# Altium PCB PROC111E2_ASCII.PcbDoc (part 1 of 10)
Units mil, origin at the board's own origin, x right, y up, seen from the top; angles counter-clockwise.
Board outline 7700 x 2300 mil, 6 copper layers (Top Layer, GND 1, SIG 1, SIG 2, GND 2, Bottom Layer), stack 78.711 mil thick; 767 components, 596 nets, 2755 pads, 1578 vias.
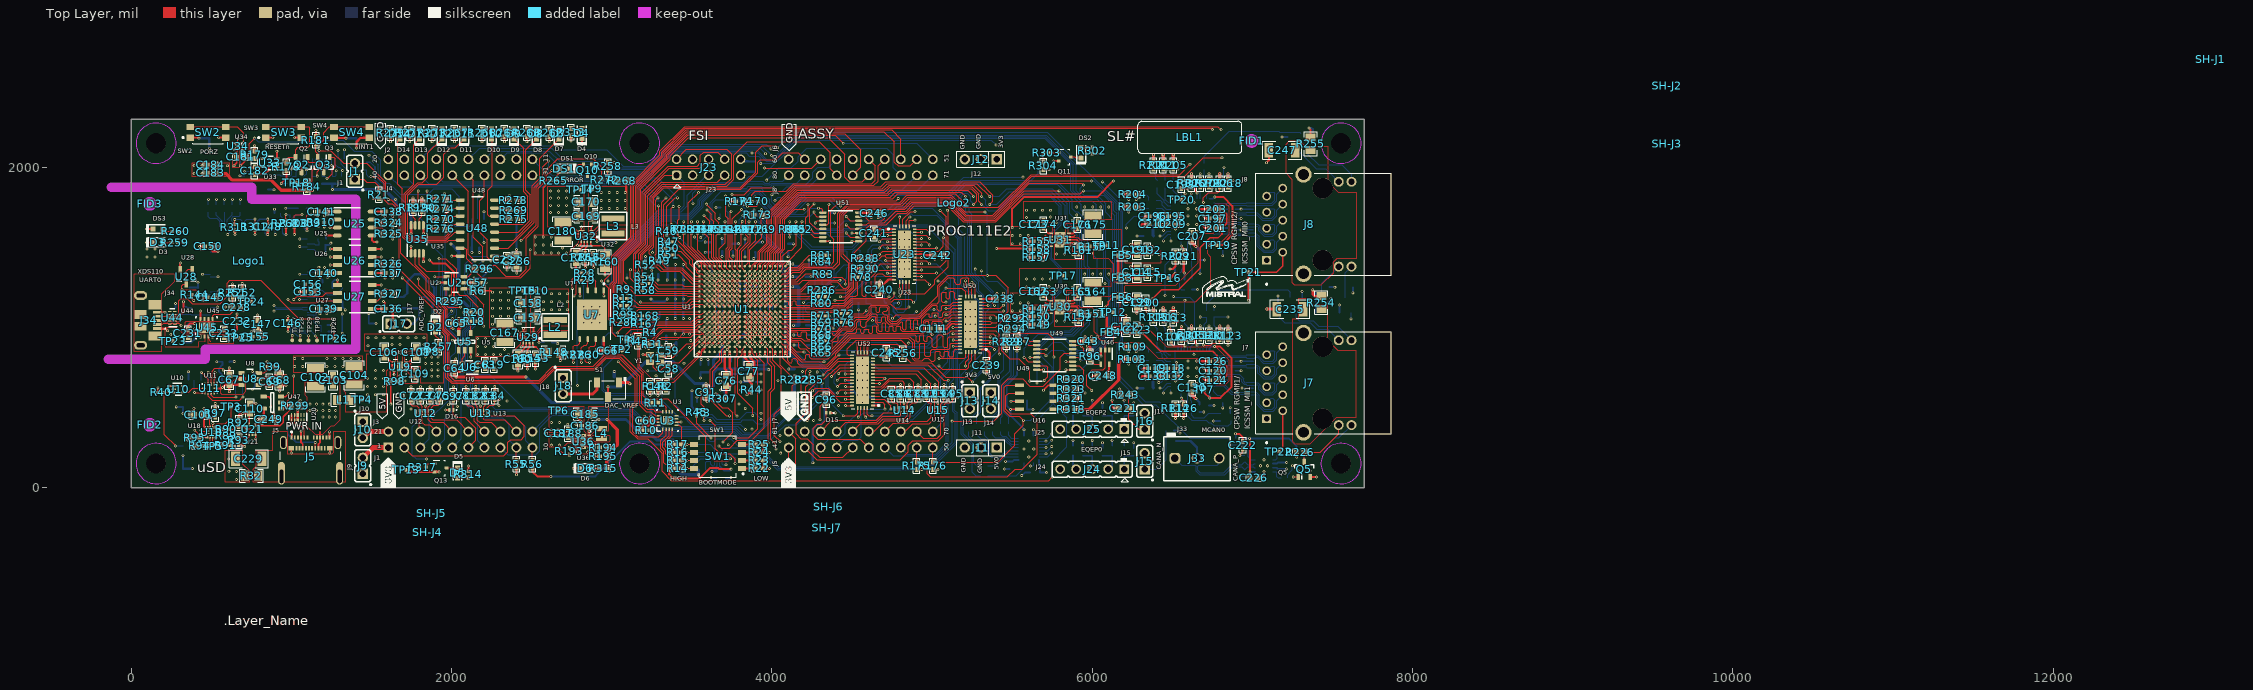
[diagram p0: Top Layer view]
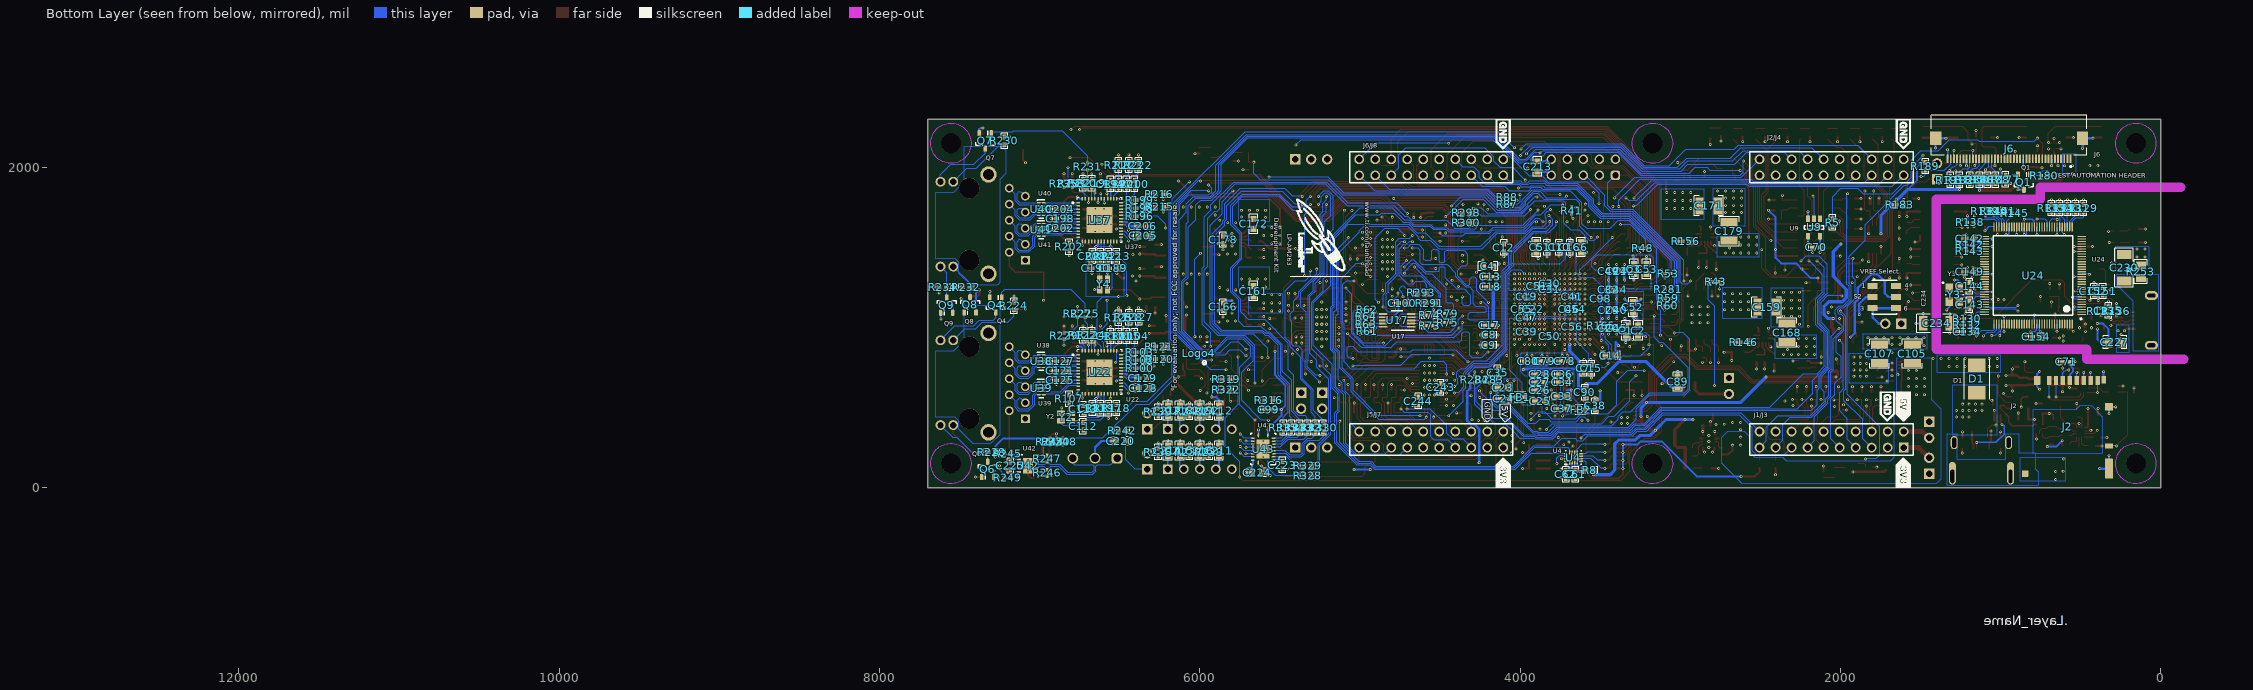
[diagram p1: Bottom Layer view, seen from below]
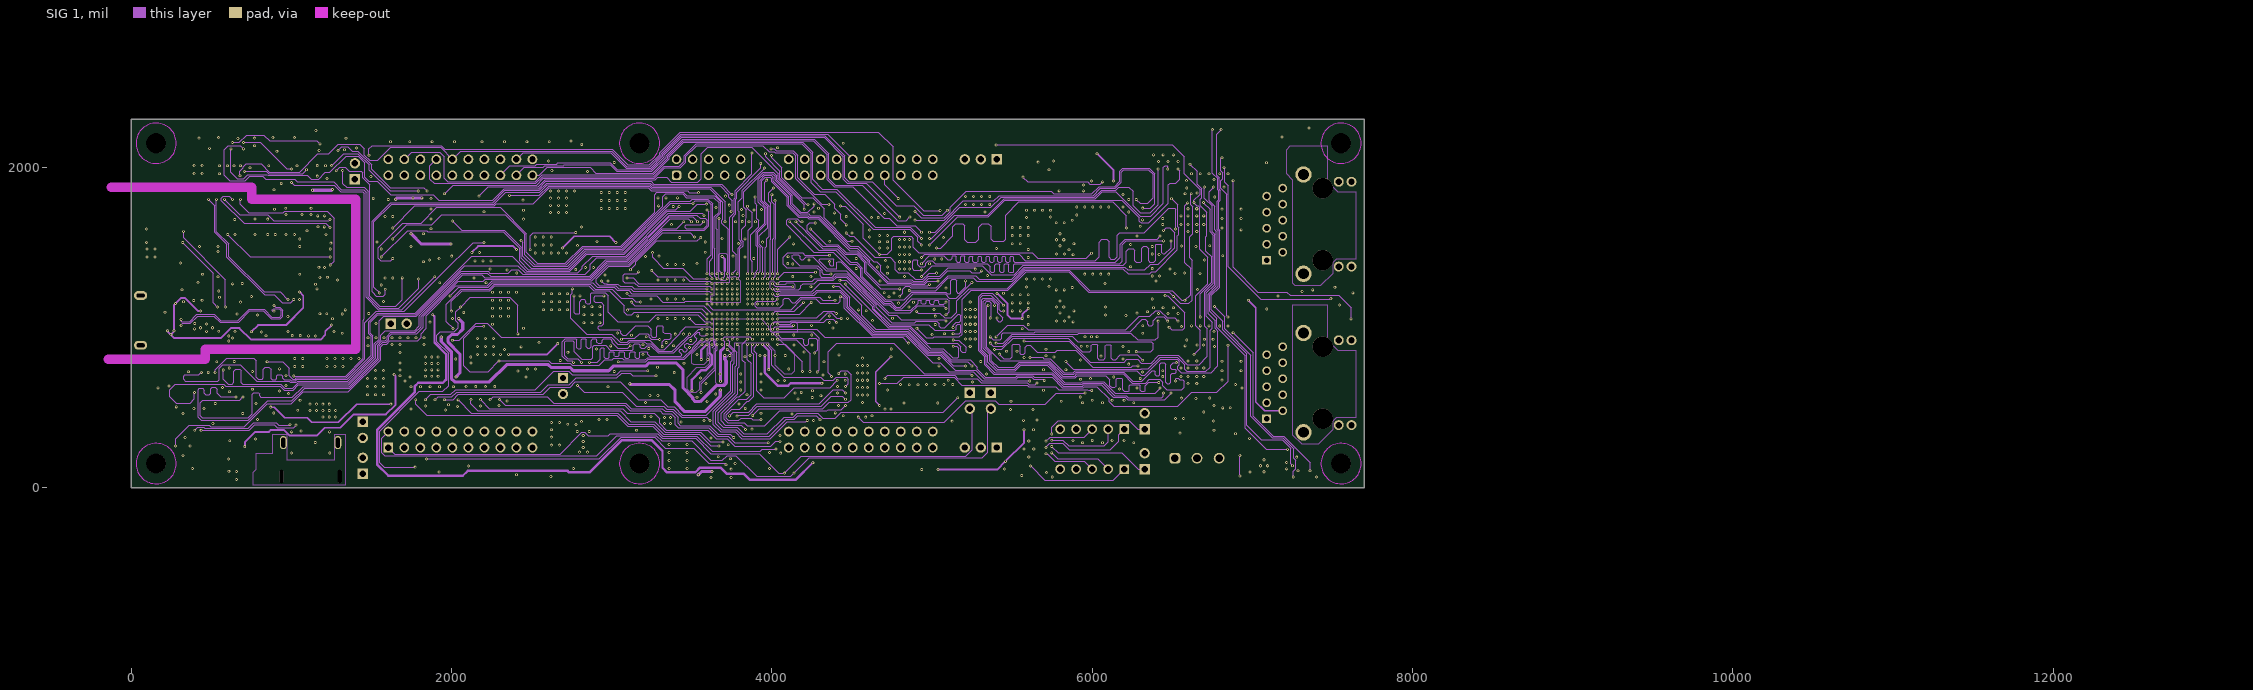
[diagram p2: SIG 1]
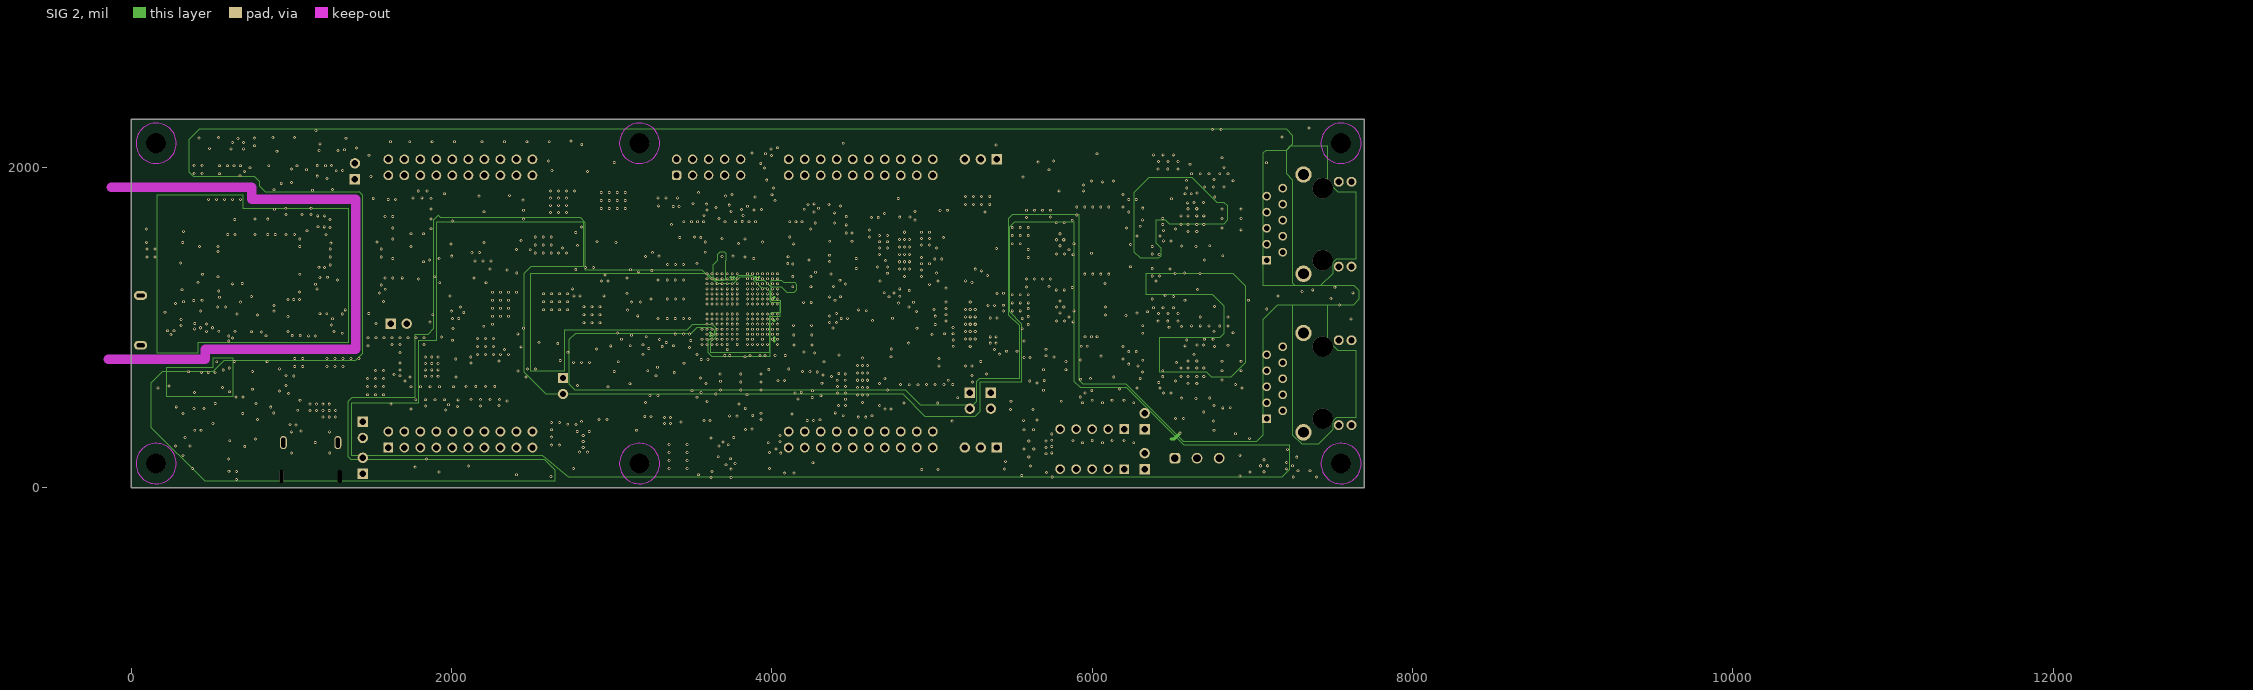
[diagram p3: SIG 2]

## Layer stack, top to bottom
Top Solder: solder mask 0.4, Solder Resist, Dk 3.5
Top Layer: signal copper 1.4
Dielectric 1: prepreg 2.8, PP-006, Dk 4.1
GND 1: signal copper 1.3779
Dielectric 3: prepreg 2.8, PP-006, Dk 4.1
SIG 1: signal copper 1.3778
Dielectric1: core 59.2, FR-4 High Tg, Dk 4.8
SIG 2: signal copper 1.3778
Dielectric 4: prepreg 2.8, PP-006, Dk 4.1
GND 2: signal copper 1.3779
Dielectric 2: prepreg 2.8, PP-006, Dk 4.1
Bottom Layer: signal copper 1.4
Bottom Solder: solder mask 0.4, Solder Resist, Dk 3.5

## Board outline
0,0 0,2300 7700,2300 7700,0

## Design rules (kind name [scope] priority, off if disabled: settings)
AssemblyTestPointUsage [All] p0: scope1count=1 scope1_0_kind=Board scope1_0_value=Board scope2count=1 scope2_0_kind=Board scope2_0_value=Board commentlength=0
AssemblyTestPointUsage [All] p1: valid=2
AssemblyTestpoint [All] p0: scope1count=1 scope1_0_kind=Board scope1_0_value=Board scope2count=1 scope2_0_kind=Board scope2_0_value=Board commentlength=0
BoardOutlineClearance [All] p0 off: scope1count=1 scope1_0_kind=Board scope1_0_value=Board scope2count=1 scope2_0_kind=Board scope2_0_value=Board commentlength=172 gap=40 // Protel DXP Scope 1 Expression Was: OnCopper and Not InComponentClass('Logo') and not InComponentClass('FiducialMark') and not InRegion(1000,500,4000,800) and not InPoly
BoardOutlineClearance BoardOutlineClearance_Poly [All] p0 off: scope1count=1 scope1_0_kind=Board scope1_0_value=Board scope2count=1 scope2_0_kind=Board scope2_0_value=Board commentlength=58 gap=25 // Protel DXP Scope 1 Expression Was: OnCopper and IsPoly
BoardOutlineClearance BoardOutlineClearance_MountingHoles [All] p0 off: scope1count=1 scope1_0_kind=Board scope1_0_value=Board scope2count=1 scope2_0_kind=Board scope2_0_value=Board commentlength=86 gap=39.37 // Protel DXP Scope 1 Expression Was: OnCopper and InComponentClass('Mounting Holes')
BoardOutlineClearance BoardOutlineClearance_MountingHoles [OnCopper and InComponentClass('Mounting Holes')] p1: gap=39.37 ignorepadtopadclearanceinfootprint=FALSE
BoardOutlineClearance BoardOutlineClearance_Poly [OnCopper and IsPoly] p2: gap=25 ignorepadtopadclearanceinfootprint=FALSE
BoardOutlineClearance [OnCopper and Not InComponentClass('Logo') and not InComponentClass('FiducialMark') and not InRegion(1000,500,4000,800) and not InPoly] p3: gap=40 ignorepadtopadclearanceinfootprint=FALSE
Clearance ADC_SIG1 [All] p0: scope1count=1 scope1_0_kind=Layer scope1_0_value=MID1 scope2count=1 scope2_0_kind=NetClass scope2_0_value=ADC0 commentlength=0 gap=7.87
Clearance ADC_EXT [All] p0 off: scope1count=1 scope1_0_kind=Board scope1_0_value=Board scope2count=1 scope2_0_kind=NetClass scope2_0_value=ADC0 commentlength=88 gap=7.87 // Protel DXP Scope 1 Expression Was: (OnLayer('Top Layer') or OnLayer('Bottom Layer'))
Clearance DIff_spacing [All] p0 off: scope1count=1 scope1_0_kind=Board scope1_0_value=Board scope2count=1 scope2_0_kind=Board scope2_0_value=Board commentlength=70 gap=7.87 // Protel DXP Scope 2 Expression Was: InDifferentialPair('XDSET_1_D')
Clearance 100E_CLR_same [All] p0 off: scope1count=1 scope1_0_kind=Board scope1_0_value=Board scope2count=1 scope2_0_kind=Board scope2_0_value=Board commentlength=70 gap=7.87 // Protel DXP Scope 1 Expression Was: InDifferentialPairClass('100E')
Clearance 100E_CLR [All] p0 off: scope1count=1 scope1_0_kind=Board scope1_0_value=Board scope2count=1 scope2_0_kind=Board scope2_0_value=Board commentlength=70 gap=7.87 // Protel DXP Scope 1 Expression Was: InDifferentialPairClass('100E')
Clearance 4mil [All] p0 off: scope1count=1 scope1_0_kind=Board scope1_0_value=Board scope2count=1 scope2_0_kind=Board scope2_0_value=Board commentlength=61 gap=4 // Protel DXP Scope 1 Expression Was: WithinRoom('SOC_4mil')
Clearance [All] p0: scope1count=1 scope1_0_kind=Board scope1_0_value=Board scope2count=1 scope2_0_kind=Board scope2_0_value=Board commentlength=0 gap=7.87
Clearance Clearance_Poly [All] p0 off: scope1count=1 scope1_0_kind=Board scope1_0_value=Board scope2count=1 scope2_0_kind=Board scope2_0_value=Board commentlength=48 gap=10 // Protel DXP Scope 1 Expression Was: InPolygon
Clearance Clearance_Keepouts [All] p0 off: scope1count=1 scope1_0_kind=Board scope1_0_value=Board scope2count=1 scope2_0_kind=Board scope2_0_value=Board commentlength=48 gap=1 // Protel DXP Scope 1 Expression Was: IsKeepOut
Clearance Clearance_Keepouts [IsKeepOut] p1: gap=1 ignorepadtopadclearanceinfootprint=FALSE
Clearance 4mil [WithinRoom('SOC_4mil')] p2: gap=4 ignorepadtopadclearanceinfootprint=TRUE except(15: Fill-Fill Fill-Poly Fill-Region Poly-Poly Poly-Region Region-Region)
Clearance ADC_EXT [(OnLayer('Top Layer') or OnLayer('Bottom Layer')) vs InNetClass('ADC0')] p3: gap=7.87 ignorepadtopadclearanceinfootprint=TRUE except(6: Via-Fill Via-Poly Via-Region; 10.6: Arc-Arc Arc-Track Track-Track; 18: Via-Via; 25: Fill-Fill Fill-Poly Fill-Region Poly-Poly Poly-Region Region-Region)
Clearance ADC_SIG1 [OnLayer('SIG 1') vs InNetClass('ADC0')] p4: gap=7.87 ignorepadtopadclearanceinfootprint=TRUE except(6: Via-Fill Via-Poly Via-Region; 9.5: Arc-Arc Arc-Track Track-Track; 18: Via-Via; 25: Fill-Fill Fill-Poly Fill-Region Poly-Poly Poly-Region Region-Region)
Clearance 100E_CLR_same [InDifferentialPairClass('100E')] p5: gap=7.87 ignorepadtopadclearanceinfootprint=TRUE except(7.7: Arc-Arc Arc-Track Track-Track; 10: Via-Fill Via-Poly Via-Region; 18: Via-Via; 25: Fill-Fill Fill-Poly Fill-Region Poly-Poly Poly-Region Region-Region)
Clearance 100E_CLR [InDifferentialPairClass('100E')] p6: gap=7.87 ignorepadtopadclearanceinfootprint=TRUE except(6: Via-Fill Via-Poly Via-Region; 16.2: Arc-Arc Arc-Track Track-Track; 18: Via-Via; 25: Fill-Fill Fill-Poly Fill-Region Poly-Poly Poly-Region Region-Region)
Clearance Clearance_Poly [InPolygon] p7: gap=10 ignorepadtopadclearanceinfootprint=TRUE except(6: Via-Fill Via-Poly Via-Region; 20: Fill-Fill Fill-Poly Fill-Region Poly-Poly Poly-Region Region-Region)
Clearance DIff_spacing [All vs InDifferentialPair('XDSET_1_D')] p8: gap=7.87 ignorepadtopadclearanceinfootprint=TRUE except(5: Arc-Arc Arc-Track Track-Track; 6: Via-Fill Via-Poly Via-Region; 18: Via-Via; 25: Fill-Fill Fill-Poly Fill-Region Poly-Poly Poly-Region Region-Region)
Clearance [All] p9: gap=7.87 ignorepadtopadclearanceinfootprint=TRUE except(5.3: Arc-Arc Arc-Track Track-Track; 6: SMDPad-SMDPad Via-Fill Via-Poly Via-Region; 7.4: Arc-SMDPad Track-SMDPad; 18: Via-Via; 25: Fill-Fill Fill-Poly Fill-Region Poly-Poly Poly-Region Region-Region)
ComponentClearance [All] p0: scope1count=1 scope1_0_kind=Board scope1_0_value=Board scope2count=1 scope2_0_kind=Board scope2_0_value=Board commentlength=0 gap=15 collisioncheckmode=3
ComponentClearance ComponentClearance_THtoTH [All] p0 off: scope1count=1 scope1_0_kind=Board scope1_0_value=Board scope2count=1 scope2_0_kind=Board scope2_0_value=Board commentlength=54 gap=20 collisioncheckmode=3 // Protel DXP Scope 2 Expression Was: IsThruComponent
ComponentClearance ComponentClearance_THtoSMT [All] p0 off: scope1count=1 scope1_0_kind=Board scope1_0_value=Board scope2count=1 scope2_0_kind=Board scope2_0_value=Board commentlength=53 gap=30 collisioncheckmode=3 // Protel DXP Scope 2 Expression Was: IsSMTComponent
ComponentClearance ComponentClearance_SmallPassives [All] p0 off: scope1count=1 scope1_0_kind=Board scope1_0_value=Board scope2count=1 scope2_0_kind=Board scope2_0_value=Board commentlength=508 gap=10 collisioncheckmode=3 // Protel DXP Scope 2 Expression Was: HasFootprint('0201*') or HasFootprint('0402*') or HasFootprint('0508') or HasFootprint('0603*') or HasFootprint('0612') or HasFootprint('0805*') or HasFootprint('0815*') or HasFootprint('0830*') or HasFootprint('1206*') or HasFootprint('1210*') or HasFootprint('1808*') or HasFootprint('1812*') or HasFootprint('1825*') or HasFootprint('2010*') or HasFootprint('2220*') or HasFootprint('2225*') or HasFootprint('2512*') or HasFootprint('2728*') or HasFootprint('3518*')
ComponentClearance ComponentClearance_MountingHoles [All] p0: scope1count=1 scope1_0_kind=ComponentClass scope1_0_value="Mounting Holes" scope2count=1 scope2_0_kind=Board scope2_0_value=Board commentlength=0 gap=100 collisioncheckmode=3
ComponentClearance ComponentClearance_ScrewToNut [All] p0 off: scope1count=1 scope1_0_kind=Board scope1_0_value=Board scope2count=1 scope2_0_kind=Board scope2_0_value=Board commentlength=71 gap=5 collisioncheckmode=3 // Protel DXP Scope 2 Expression Was: (HasFootprint('Keystone_1902C'))
ComponentClearance ComponentClearance_Logo [All] p0: scope1count=1 scope1_0_kind=ComponentClass scope1_0_value=Logo scope2count=1 scope2_0_kind=Board scope2_0_value=Board commentlength=0 gap=30 collisioncheckmode=3
ComponentClearance ComponentClearance_Shunt [All] p0: scope1count=1 scope1_0_kind=ComponentClass scope1_0_value=Header scope2count=1 scope2_0_kind=ComponentClass scope2_0_value=Shunt commentlength=0 gap=0 collisioncheckmode=3
ComponentClearance ComponentClearance_MountingHoles_FiducialMarks [All] p0: scope1count=1 scope1_0_kind=ComponentClass scope1_0_value="Mounting Holes" scope2count=1 scope2_0_kind=ComponentClass scope2_0_value=FiducialMark commentlength=0 gap=50 collisioncheckmode=3
ComponentClearance ComponentClearance_MountingHoles_FiducialMarks [InComponentClass('Mounting Holes') vs InComponentClass('FiducialMark')] p1: gap=50 collisioncheckmode=3 verticalgap=10 showdistances=FALSE
ComponentClearance ComponentClearance_Shunt [InComponentClass('Header') vs InComponentClass('Shunt')] p2: gap=0 collisioncheckmode=3 verticalgap=0 showdistances=FALSE
ComponentClearance ComponentClearance_Logo [InComponentClass('Logo')] p3: gap=30 collisioncheckmode=3 verticalgap=10 showdistances=FALSE
ComponentClearance ComponentClearance_ScrewToNut [(HasFootprint('NY PMS 440 0025 PH')) vs (HasFootprint('Keystone_1902C'))] p4: gap=5 collisioncheckmode=3 verticalgap=10 showdistances=FALSE
ComponentClearance ComponentClearance_MountingHoles [InComponentClass('Mounting Holes')] p5: gap=100 collisioncheckmode=3 verticalgap=100000 showdistances=FALSE
ComponentClearance ComponentClearance_SmallPassives [HasFootprint('0201*') or HasFootprint('0402*') or HasFootprint('0508') or HasFootprint('0603*') or HasFootprint('0612') or HasFootprint('0805*') or HasFootprint('0815*') or HasFootprint('0830*') or HasFootprint('1206*') or HasFootprint('1210*') or HasFootprint('1808*') or HasFootprint('1812*') or HasFootprint('1825*') or HasFootprint('2010*') or HasFootprint('2220*') or HasFootprint('2225*') or HasFootprint('2512*') or HasFootprint('2728*') or HasFootprint('3518*') vs HasFootprint('0201*') or HasFootprint('0402*') or HasFootprint('0508') or HasFootprint('0603*') or HasFootprint('0612') or HasFootprint('0805*') or HasFootprint('0815*') or HasFootprint('0830*') or HasFootprint('1206*') or HasFootprint('1210*') or HasFootprint('1808*') or HasFootprint('1812*') or HasFootprint('1825*') or HasFootprint('2010*') or HasFootprint('2220*') or HasFootprint('2225*') or HasFootprint('2512*') or HasFootprint('2728*') or HasFootprint('3518*')] p6: gap=10 collisioncheckmode=3 verticalgap=10 showdistances=FALSE
ComponentClearance ComponentClearance_THtoSMT [IsThruComponent vs IsSMTComponent] p7: gap=30 collisioncheckmode=3 verticalgap=30 showdistances=FALSE
ComponentClearance ComponentClearance_THtoTH [IsThruComponent vs IsThruComponent] p8: gap=20 collisioncheckmode=3 verticalgap=30 showdistances=FALSE
ComponentClearance [All] p9: gap=15 collisioncheckmode=3 verticalgap=15 showdistances=TRUE
DiffPairsRouting 90E [All] p0 off: scope1count=1 scope1_0_kind=Board scope1_0_value=Board scope2count=1 scope2_0_kind=Board scope2_0_value=Board commentlength=70 // Protel DXP Scope 1 Expression Was: InDifferentialPair('XDSET_1_D')
DiffPairsRouting 120E [All] p0 off: scope1count=1 scope1_0_kind=Board scope1_0_value=Board scope2count=1 scope2_0_kind=Board scope2_0_value=Board commentlength=65 // Protel DXP Scope 1 Expression Was: InDifferentialPair('CANA')
DiffPairsRouting 100E_DIFF [All] p0 off: scope1count=1 scope1_0_kind=Board scope1_0_value=Board scope2count=1 scope2_0_kind=Board scope2_0_value=Board commentlength=70 // Protel DXP Scope 1 Expression Was: InDifferentialPairClass('100E')
DiffPairsRouting 90E [InDifferentialPair('XDSET_1_D')] p1: maxlimit=10 minlimit=5 mostfreqgap=10 toplayer_prefgap=5 toplayer_minwidth=4.2 toplayer_maxwidth=15 toplayer_prefwidth=4.2 midlayer1_mingap=6 midlayer1_maxgap=6 midlayer1_prefgap=6 midlayer1_minwidth=4 midlayer1_maxwidth=4 midlayer1_prefwidth=4 midlayer2_mingap=10 midlayer2_minwidth=15 midlayer2_maxwidth=15 midlayer2_prefwidth=15 midlayer3_mingap=10 midlayer3_minwidth=15 midlayer3_maxwidth=15 midlayer3_prefwidth=15 midlayer4_mingap=10 midlayer4_minwidth=15 midlayer4_maxwidth=15 midlayer4_prefwidth=15 bottomlayer_prefgap=5 bottomlayer_minwidth=4.2 bottomlayer_maxwidth=15 bottomlayer_prefwidth=4.2 maxuncoupledlength=500
DiffPairsRouting 120E [InDifferentialPair('CANA')] p2: maxlimit=10 minlimit=6.8 mostfreqgap=10 toplayer_prefgap=6.8 toplayer_minwidth=4.1 toplayer_maxwidth=15 toplayer_prefwidth=4.1 midlayer1_mingap=10 midlayer1_minwidth=15 midlayer1_maxwidth=15 midlayer1_prefwidth=15 midlayer2_mingap=10 midlayer2_minwidth=15 midlayer2_maxwidth=15 midlayer2_prefwidth=15 midlayer3_mingap=10 midlayer3_minwidth=15 midlayer3_maxwidth=15 midlayer3_prefwidth=15 midlayer4_mingap=10 midlayer4_minwidth=15 midlayer4_maxwidth=15 midlayer4_prefwidth=15 bottomlayer_prefgap=6.8 bottomlayer_minwidth=4.1 bottomlayer_maxwidth=15 bottomlayer_prefwidth=4.1 maxuncoupledlength=500
DiffPairsRouting 100E_DIFF [InDifferentialPairClass('100E')] p3: maxlimit=100 minlimit=7.7 mostfreqgap=10 toplayer_maxgap=7.7 toplayer_prefgap=7.7 toplayer_minwidth=4 toplayer_maxwidth=4 toplayer_prefwidth=4 midlayer1_mingap=8.1 midlayer1_maxgap=8.1 midlayer1_prefgap=8.1 midlayer1_minwidth=3.5 midlayer1_maxwidth=3.5 midlayer1_prefwidth=3.5 midlayer2_mingap=10 midlayer2_minwidth=15 midlayer2_maxwidth=15 midlayer2_prefwidth=15 midlayer3_mingap=10 midlayer3_minwidth=15 midlayer3_maxwidth=15 midlayer3_prefwidth=15 midlayer4_mingap=10 midlayer4_minwidth=15 midlayer4_maxwidth=15 midlayer4_prefwidth=15 bottomlayer_maxgap=7.7 bottomlayer_prefgap=7.7 bottomlayer_minwidth=4 bottomlayer_maxwidth=4 bottomlayer_prefwidth=4 maxuncoupledlength=1000
FabricationTestPointUsage TestPointUsage [All] p0: scope1count=1 scope1_0_kind=Board scope1_0_value=Board scope2count=1 scope2_0_kind=Board scope2_0_value=Board commentlength=0 valid=2 allowmultiple=FALSE
FabricationTestPointUsage TestPointUsage [All] p1: valid=2 allowmultiple=FALSE
FabricationTestpoint Testpoint [All] p0: scope1count=1 scope1_0_kind=Board scope1_0_value=Board scope2count=1 scope2_0_kind=Board scope2_0_value=Board commentlength=0 side=3 testpointundercomponent=TRUE minsize=40 maxsize=100 preferedsize=60 minholesize=0 maxholesize=40 preferedholesize=32 testpointgrid=1
FabricationTestpoint Testpoint [All] p1: side=3 testpointundercomponent=TRUE minsize=40 maxsize=100 preferedsize=60 minholesize=0 maxholesize=40 preferedholesize=32 testpointgrid=1 allowsidetop=TRUE allowsidebottom=TRUE usegrid=TRUE gridtolerance=0.01
FanoutControl Fanout_Small [All] p0 off: scope1count=1 scope1_0_kind=Board scope1_0_value=Board scope2count=1 scope2_0_kind=Board scope2_0_value=Board commentlength=84 // Protel DXP Scope 1 Expression Was: (CompPinCount < 5)   Fanout_Small (Default Rule)
FanoutControl Fanout_Default [All] p0: scope1count=1 scope1_0_kind=Board scope1_0_value=Board scope2count=1 scope2_0_kind=Board scope2_0_value=Board commentlength=30 // Fanout_Default (Default Rule)
FanoutControl Fanout_SOIC [All] p0 off: scope1count=1 scope1_0_kind=Board scope1_0_value=Board scope2count=1 scope2_0_kind=Board scope2_0_value=Board commentlength=71 // Protel DXP Scope 1 Expression Was: IsSOIC   Fanout_SOIC (Default Rule)
FanoutControl Fanout_BGA [All] p0 off: scope1count=1 scope1_0_kind=Board scope1_0_value=Board scope2count=1 scope2_0_kind=Board scope2_0_value=Board commentlength=69 // Protel DXP Scope 1 Expression Was: IsBGA   Fanout_BGA (Default Rule)
FanoutControl Fanout_LCC [All] p0 off: scope1count=1 scope1_0_kind=Board scope1_0_value=Board scope2count=1 scope2_0_kind=Board scope2_0_value=Board commentlength=69 // Protel DXP Scope 1 Expression Was: IsLCC   Fanout_LCC (Default Rule)
FanoutControl Fanout_LCC [IsLCC] p1: bgadir=Out bgaviamode=Centered fanoutstyle=Auto fanoutdirection=Alternating viagrid=1 // Fanout_LCC (Default Rule)
FanoutControl Fanout_BGA [IsBGA] p2: bgadir=Out bgaviamode=Centered fanoutstyle=Auto fanoutdirection=Alternating viagrid=1 // Fanout_BGA (Default Rule)
FanoutControl Fanout_Default [All] p4: bgadir=Out bgaviamode=Centered fanoutstyle=Auto fanoutdirection=Alternating viagrid=1 // Fanout_Default (Default Rule)
FanoutControl Fanout_Small [(CompPinCount < 5)] p5: bgadir=Out bgaviamode=Centered fanoutstyle=Auto fanoutdirection=OutThenIn viagrid=1 // Fanout_Small (Default Rule)
Height [All] p0: scope1count=1 scope1_0_kind=Board scope1_0_value=Board scope2count=1 scope2_0_kind=Board scope2_0_value=Board commentlength=0
HoleSize [All] p0: scope1count=1 scope1_0_kind=Board scope1_0_value=Board scope2count=1 scope2_0_kind=Board scope2_0_value=Board commentlength=0 absolutevalues=TRUE maxlimit=251 minlimit=7.87 maxpercent=80.000 minpercent=20.000
HoleSize [All] p1: absolutevalues=TRUE maxlimit=251 minlimit=7.87 maxpercent=80.000 minpercent=20.000
HoleToHoleClearance [All] p0: scope1count=1 scope1_0_kind=Board scope1_0_value=Board scope2count=1 scope2_0_kind=Board scope2_0_value=Board commentlength=0
LayerPairs [All] p0: scope1count=1 scope1_0_kind=Board scope1_0_value=Board scope2count=1 scope2_0_kind=Board scope2_0_value=Board commentlength=0 enforce=TRUE
MatchedLengths PRO_PROU_GPIO(11-16) [All] p0 off: scope1count=1 scope1_0_kind=Board scope1_0_value=Board scope2count=1 scope2_0_kind=Board scope2_0_value=Board commentlength=77 tolerance=7.5 amplitude=200 gap=20 style=90-Degree // Protel DXP Scope 1 Expression Was: InxSignalClass('PRO_PROU_GPIO(11-16)')
MatchedLengths PRO_PROU_GPIO(0-6) [All] p0 off: scope1count=1 scope1_0_kind=Board scope1_0_value=Board scope2count=1 scope2_0_kind=Board scope2_0_value=Board commentlength=75 tolerance=7.5 amplitude=200 gap=20 style=90-Degree // Protel DXP Scope 1 Expression Was: InxSignalClass('PRO_PROU_GPIO(0-6)')
MatchedLengths AM263_RGMII1_RX [All] p0 off: scope1count=1 scope1_0_kind=Board scope1_0_value=Board scope2count=1 scope2_0_kind=Board scope2_0_value=Board commentlength=72 tolerance=7.5 amplitude=200 gap=20 style=90-Degree // Protel DXP Scope 1 Expression Was: InxSignalClass('AM263_RGMII1_RX')
MatchedLengths AM263_RGMII1_TX [All] p0 off: scope1count=1 scope1_0_kind=Board scope1_0_value=Board scope2count=1 scope2_0_kind=Board scope2_0_value=Board commentlength=72 tolerance=7.5 amplitude=200 gap=20 style=90-Degree // Protel DXP Scope 1 Expression Was: InxSignalClass('AM263_RGMII1_TX')
MatchedLengths ICSSM_MII1_RX [All] p0 off: scope1count=1 scope1_0_kind=Board scope1_0_value=Board scope2count=1 scope2_0_kind=Board scope2_0_value=Board commentlength=70 tolerance=7.5 amplitude=200 gap=20 style=90-Degree // Protel DXP Scope 1 Expression Was: InxSignalClass('ICSSM_MII1_RX')
MatchedLengths ICSSM_MII1_TX [All] p0 off: scope1count=1 scope1_0_kind=Board scope1_0_value=Board scope2count=1 scope2_0_kind=Board scope2_0_value=Board commentlength=70 tolerance=7.5 amplitude=200 gap=20 style=90-Degree // Protel DXP Scope 1 Expression Was: InxSignalClass('ICSSM_MII1_TX')
MatchedLengths ICSSM_MII0_TX [All] p0 off: scope1count=1 scope1_0_kind=Board scope1_0_value=Board scope2count=1 scope2_0_kind=Board scope2_0_value=Board commentlength=70 tolerance=7.5 amplitude=200 gap=20 style=90-Degree // Protel DXP Scope 1 Expression Was: InxSignalClass('ICSSM_MII0_TX')
MatchedLengths ICSSM_MII0_RX [All] p0 off: scope1count=1 scope1_0_kind=Board scope1_0_value=Board scope2count=1 scope2_0_kind=Board scope2_0_value=Board commentlength=70 tolerance=7.5 amplitude=200 gap=20 style=90-Degree // Protel DXP Scope 1 Expression Was: InxSignalClass('ICSSM_MII0_RX')
MatchedLengths ETH1_TX [All] p0 off: scope1count=1 scope1_0_kind=Board scope1_0_value=Board scope2count=1 scope2_0_kind=Board scope2_0_value=Board commentlength=64 tolerance=7.5 amplitude=200 gap=20 style=90-Degree // Protel DXP Scope 1 Expression Was: InxSignalClass('ETH1_TX')
MatchedLengths ETH1_RX [All] p0 off: scope1count=1 scope1_0_kind=Board scope1_0_value=Board scope2count=1 scope2_0_kind=Board scope2_0_value=Board commentlength=64 tolerance=7.5 amplitude=200 gap=20 style=90-Degree // Protel DXP Scope 1 Expression Was: InxSignalClass('ETH1_RX')
MatchedLengths DIFF [All] p0: scope1count=1 scope1_0_kind=Board scope1_0_value=Board scope2count=1 scope2_0_kind=Board scope2_0_value=Board commentlength=0 tolerance=2 amplitude=200 gap=20 style=90-Degree
MatchedLengths "SD CARD" [All] p0 off: scope1count=1 scope1_0_kind=Board scope1_0_value=Board scope2count=1 scope2_0_kind=Board scope2_0_value=Board commentlength=61 tolerance=25 amplitude=200 gap=20 style=90-Degree // Protel DXP Scope 1 Expression Was: InxSignalClass('MMC0')
MatchedLengths QSPI [All] p0 off: scope1count=1 scope1_0_kind=Board scope1_0_value=Board scope2count=1 scope2_0_kind=Board scope2_0_value=Board commentlength=67 tolerance=25 amplitude=200 gap=20 style=90-Degree // Protel DXP Scope 1 Expression Was: InxSignalClass('QSPI_FLASH')
MatchedLengths DIFF [All] p1: tolerance=2 checknetsindiffpair=TRUE checkdiffpairvsdiffpair=FALSE checkxsignals=FALSE checkothers=FALSE
MatchedLengths QSPI [InxSignalClass('QSPI_FLASH')] p2: tolerance=25 checknetsindiffpair=FALSE checkdiffpairvsdiffpair=TRUE checkxsignals=TRUE checkothers=TRUE
MatchedLengths ETH1_RX [InxSignalClass('ETH1_RX')] p3: tolerance=7.5 checknetsindiffpair=FALSE checkdiffpairvsdiffpair=TRUE checkxsignals=TRUE checkothers=TRUE
MatchedLengths ETH1_TX [InxSignalClass('ETH1_TX')] p4: tolerance=7.5 checknetsindiffpair=FALSE checkdiffpairvsdiffpair=TRUE checkxsignals=TRUE checkothers=TRUE
MatchedLengths ICSSM_MII0_RX [InxSignalClass('ICSSM_MII0_RX')] p5: tolerance=7.5 checknetsindiffpair=FALSE checkdiffpairvsdiffpair=TRUE checkxsignals=TRUE checkothers=TRUE
MatchedLengths AM263_RGMII1_TX [InxSignalClass('AM263_RGMII1_TX')] p6: tolerance=7.5 checknetsindiffpair=FALSE checkdiffpairvsdiffpair=TRUE checkxsignals=TRUE checkothers=TRUE
MatchedLengths PRO_PROU_GPIO(0-6) [InxSignalClass('PRO_PROU_GPIO(0-6)')] p7: tolerance=7.5 checknetsindiffpair=FALSE checkdiffpairvsdiffpair=TRUE checkxsignals=TRUE checkothers=TRUE
MatchedLengths PRO_PROU_GPIO(11-16) [InxSignalClass('PRO_PROU_GPIO(11-16)')] p8: tolerance=7.5 checknetsindiffpair=FALSE checkdiffpairvsdiffpair=TRUE checkxsignals=TRUE checkothers=TRUE
MatchedLengths AM263_RGMII1_RX [InxSignalClass('AM263_RGMII1_RX')] p9: tolerance=7.5 checknetsindiffpair=FALSE checkdiffpairvsdiffpair=TRUE checkxsignals=TRUE checkothers=TRUE
MatchedLengths ICSSM_MII0_TX [InxSignalClass('ICSSM_MII0_TX')] p10: tolerance=7.5 checknetsindiffpair=FALSE checkdiffpairvsdiffpair=TRUE checkxsignals=TRUE checkothers=TRUE
MatchedLengths ICSSM_MII1_TX [InxSignalClass('ICSSM_MII1_TX')] p11: tolerance=7.5 checknetsindiffpair=FALSE checkdiffpairvsdiffpair=TRUE checkxsignals=TRUE checkothers=TRUE
MatchedLengths ICSSM_MII1_RX [InxSignalClass('ICSSM_MII1_RX')] p12: tolerance=7.5 checknetsindiffpair=FALSE checkdiffpairvsdiffpair=TRUE checkxsignals=TRUE checkothers=TRUE
MatchedLengths "SD CARD" [InxSignalClass('MMC0')] p13: tolerance=25 checknetsindiffpair=FALSE checkdiffpairvsdiffpair=TRUE checkxsignals=TRUE checkothers=TRUE
MinimumAnnularRing [All] p0: scope1count=1 scope1_0_kind=Board scope1_0_value=Board scope2count=1 scope2_0_kind=Board scope2_0_value=Board commentlength=0 minimumring=5
MinimumAnnularRing MinimumAnnularRing_ThermalPadVias [All] p0 off: scope1count=1 scope1_0_kind=Board scope1_0_value=Board scope2count=1 scope2_0_kind=Board scope2_0_value=Board commentlength=63 minimumring=5.91 // Protel DXP Scope 1 Expression Was: IsVia and InAnyComponent
MinimumAnnularRing MinimumAnnularRing_ThermalPadVias [IsVia and InAnyComponent] p1: minimumring=5.91
MinimumAnnularRing [All] p2: minimumring=5
MinimumSolderMaskSliver MinimumSolderMaskSliver_Logo [All] p0: scope1count=1 scope1_0_kind=ComponentClass scope1_0_value=Logo scope2count=1 scope2_0_kind=ComponentClass scope2_0_value=Logo commentlength=0
MinimumSolderMaskSliver MinimumSolderMaskSliver_Logo [InComponentClass('Logo') vs InComponentClass('Logo')] p1: minsoldermaskwidth=0.7
NetAntennae [All] p0: scope1count=1 scope1_0_kind=Board scope1_0_value=Board scope2count=1 scope2_0_kind=Board scope2_0_value=Board commentlength=0
PasteMaskExpansion [All] p0: scope1count=1 scope1_0_kind=Board scope1_0_value=Board scope2count=1 scope2_0_kind=Board scope2_0_value=Board commentlength=0 expansion=0
PlaneClearance [All] p0: scope1count=1 scope1_0_kind=Board scope1_0_value=Board scope2count=1 scope2_0_kind=Board scope2_0_value=Board commentlength=0 clearance=20
PlaneConnect [All] p0: scope1count=1 scope1_0_kind=Board scope1_0_value=Board scope2count=1 scope2_0_kind=Board scope2_0_value=Board commentlength=0 planeconnectstyle=Direct reliefexpansion=10 reliefentries=4 reliefconductorwidth=10 reliefairgap=10
PlaneConnect [All] p1: planeconnectstyle=Direct reliefexpansion=10 reliefentries=4 reliefconductorwidth=10 reliefairgap=10
PolygonConnect PolygonConnect_3 [All] p0 off: scope1count=1 scope1_0_kind=Board scope1_0_value=Board scope2count=1 scope2_0_kind=Board scope2_0_value=Board commentlength=71 connectstyle=Direct reliefconductorwidth=10 reliefentries=4 polygonreliefangle="90 Angle" // Protel DXP Scope 2 Expression Was: IsNamedPolygon('SIG 2-vusb_3v3')
PolygonConnect PolygonConnect_2 [All] p0 off: scope1count=1 scope1_0_kind=Board scope1_0_value=Board scope2count=1 scope2_0_kind=Board scope2_0_value=Board commentlength=81 connectstyle=Direct reliefconductorwidth=10 reliefentries=4 polygonreliefangle="90 Angle" // Protel DXP Scope 2 Expression Was: IsNamedPolygon('Top Layer-VBUS_TYPEC_5V0')
PolygonConnect PolygonConnect_1 [All] p0 off: scope1count=1 scope1_0_kind=Board scope1_0_value=Board scope2count=1 scope2_0_kind=Board scope2_0_value=Board commentlength=81 connectstyle=Direct reliefconductorwidth=10 reliefentries=4 polygonreliefangle="90 Angle" // Protel DXP Scope 2 Expression Was: IsNamedPolygon('Top Layer-VBUS_TYPEC_5V0')
PolygonConnect [All] p0: scope1count=1 scope1_0_kind=Board scope1_0_value=Board scope2count=1 scope2_0_kind=Board scope2_0_value=Board commentlength=0 connectstyle=Direct reliefconductorwidth=10 reliefentries=4 polygonreliefangle="90 Angle"
PolygonConnect PolygonConnect_3 [All vs IsNamedPolygon('SIG 2-vusb_3v3')] p1: connectstyle=Direct reliefconductorwidth=10 reliefentries=4 polygonreliefangle="90 Angle" airgapwidth=10
PolygonConnect PolygonConnect_2 [All vs IsNamedPolygon('Top Layer-VBUS_TYPEC_5V0')] p2: connectstyle=Direct reliefconductorwidth=10 reliefentries=4 polygonreliefangle="90 Angle" airgapwidth=10
PolygonConnect PolygonConnect_1 [All vs IsNamedPolygon('Top Layer-VBUS_TYPEC_5V0')] p3: connectstyle=Direct reliefconductorwidth=10 reliefentries=4 polygonreliefangle="90 Angle" airgapwidth=10
PolygonConnect [All] p4: connectstyle=Direct reliefconductorwidth=10 reliefentries=4 polygonreliefangle="90 Angle" airgapwidth=10
RoomDefinition SOC_4mil [All] p0 off: scope1count=1 scope1_0_kind=Board scope1_0_value=Board scope2count=1 scope2_0_kind=Board scope2_0_value=Board commentlength=44 region_x1=42076367 region_y1=23498658 region_x2=48060626 region_y2=29482917 confinementstyle=ConfineIn // Protel DXP Scope 1 Expression Was: False
RoomDefinition SOC_4mil [False] p1: confinementstyle=ConfineIn formatcopy=TRUE lockcomponents=FALSE outline 3515.64,815.87 4114.06,815.87 4114.06,1414.29 3515.64,1414.29
RoutingCorners [All] p0: scope1count=1 scope1_0_kind=Board scope1_0_value=Board scope2count=1 scope2_0_kind=Board scope2_0_value=Board commentlength=0 cornerstyle=45-Degree minsetback=100 maxsetback=100
RoutingLayers [All] p0: scope1count=1 scope1_0_kind=Board scope1_0_value=Board scope2count=1 scope2_0_kind=Board scope2_0_value=Board commentlength=0 top layer=Automatic mid layer 1=Automatic mid layer 2=Automatic mid layer 3=Automatic mid layer 4=Automatic bottom layer=Automatic
RoutingLayers [All] p1: top layer_v5=TRUE mid layer 1_v5=TRUE mid layer 2_v5=TRUE mid layer 3_v5=FALSE mid layer 4_v5=TRUE bottom layer_v5=TRUE
RoutingPriority [All] p0: scope1count=1 scope1_0_kind=Board scope1_0_value=Board scope2count=1 scope2_0_kind=Board scope2_0_value=Board commentlength=0
RoutingTopology [All] p0: scope1count=1 scope1_0_kind=Board scope1_0_value=Board scope2count=1 scope2_0_kind=Board scope2_0_value=Board commentlength=0 topology=Shortest
RoutingVias [All] p0: scope1count=1 scope1_0_kind=Board scope1_0_value=Board scope2count=1 scope2_0_kind=Board scope2_0_value=Board commentlength=0 holewidth=8 width=18 viastyle="Through Hole" minholewidth=8 minwidth=18 maxholewidth=8 maxwidth=18
RoutingVias ThermalPadVias [All] p0 off: scope1count=1 scope1_0_kind=Board scope1_0_value=Board scope2count=1 scope2_0_kind=Board scope2_0_value=Board commentlength=63 holewidth=7.87 width=19.68 viastyle="Through Hole" minholewidth=7.87 minwidth=19.68 maxholewidth=12.99 maxwidth=23.62 // Protel DXP Scope 1 Expression Was: IsVia and InAnyComponent
RoutingVias ThermalPadVias [IsVia and InAnyComponent] p1: holewidth=7.87 width=19.68 viastyle="Through Hole" minholewidth=7.87 minwidth=19.68 maxholewidth=12.99 maxwidth=23.62
RoutingVias [All] p2: holewidth=8 width=18 viastyle="Through Hole" minholewidth=8 minwidth=18 maxholewidth=8 maxwidth=18
ShortCircuit [All] p0: scope1count=1 scope1_0_kind=Board scope1_0_value=Board scope2count=1 scope2_0_kind=Board scope2_0_value=Board commentlength=0 allowed=FALSE
SilkToBoardRegionClearance [All] p0 off: scope1count=1 scope1_0_kind=Board scope1_0_value=Board scope2count=1 scope2_0_kind=Board scope2_0_value=Board commentlength=130 // Protel DXP Scope 1 Expression Was: Not ((IsComment or IsDesignator) And (Hide <> 'False')) and not InRegion(1000,500,4000,800)
SilkToBoardRegionClearance [Not ((IsComment or IsDesignator) And (Hide <> 'False')) and not InRegion(1000,500,4000,800)] p1:
SilkToSilkClearance [All] p0: scope1count=1 scope1_0_kind=Board scope1_0_value=Board scope2count=1 scope2_0_kind=Board scope2_0_value=Board commentlength=0
SilkToSilkClearance SilkToSilkClearance_Pb-FreeLogo [All] p0 off: scope1count=1 scope1_0_kind=Board scope1_0_value=Board scope2count=1 scope2_0_kind=Board scope2_0_value=Board commentlength=120 // Protel DXP Scope 2 Expression Was: (HasFootprint('Pb-Free_Overlay_Medium') OR HasFootprint('Pb-Free_Overlay_Small'))
SilkToSilkClearance SilkToSilkClearance_Pb-FreeLogo [(HasFootprint('Pb-Free_Overlay_Medium') OR HasFootprint('Pb-Free_Overlay_Small')) vs (HasFootprint('Pb-Free_Overlay_Medium') OR HasFootprint('Pb-Free_Overlay_Small'))] p1: silktosilkclearance=0
SilkToSilkClearance [All] p2: silktosilkclearance=3.94
SilkToSolderMaskClearance "Silk to Solder Mask Opening" [All] p0: scope1count=1 scope1_0_kind=Board scope1_0_value=Board scope2count=1 scope2_0_kind=Board scope2_0_value=Board commentlength=0
SilkToSolderMaskClearance SilkToComponentPadClearance [All] p0 off: scope1count=1 scope1_0_kind=Board scope1_0_value=Board scope2count=1 scope2_0_kind=Board scope2_0_value=Board commentlength=82 // Protel DXP Scope 1 Expression Was: (IsPad or IsFill or IsRegion) and Component
SilkToSolderMaskClearance SilkToComponentPadClearance [(IsPad or IsFill or IsRegion) and Component] p1: minsilkscreentomaskgap=3.54 clearancetoexposedcopper=TRUE
SilkToSolderMaskClearance "Silk to Solder Mask Opening" [All] p2: minsilkscreentomaskgap=3 clearancetoexposedcopper=FALSE
SolderMaskExpansion [All] p0: scope1count=1 scope1_0_kind=Board scope1_0_value=Board scope2count=1 scope2_0_kind=Board scope2_0_value=Board commentlength=0 expansion=1.97
SolderMaskExpansion [All] p1: expansion=1.97 istentingtop=FALSE
UnRoutedNet [All] p0: scope1count=1 scope1_0_kind=Board scope1_0_value=Board scope2count=1 scope2_0_kind=Board scope2_0_value=Board commentlength=0
UnRoutedNet [All] p1: checkbadconnections=TRUE
UnpouredPolygon [All] p0: scope1count=1 scope1_0_kind=Board scope1_0_value=Board scope2count=1 scope2_0_kind=Board scope2_0_value=Board commentlength=0
Width "4 mil_mux" [All] p0 off: scope1count=1 scope1_0_kind=Board scope1_0_value=Board scope2count=1 scope2_0_kind=Board scope2_0_value=Board commentlength=120 maxlimit=15 minlimit=4.75 preferedwidth=10 // Protel DXP Scope 1 Expression Was: WithinRoom('SOC_4mil_1') or  WithinRoom('SOC_4mil_2') or WithinRoom('SOC_4mil_3')
Width 4mil_soc [All] p0 off: scope1count=1 scope1_0_kind=Board scope1_0_value=Board scope2count=1 scope2_0_kind=Board scope2_0_value=Board commentlength=61 maxlimit=20 minlimit=4 preferedwidth=15 // Protel DXP Scope 1 Expression Was: WithinRoom('SOC_4mil')
Width PWR [All] p0: scope1count=1 scope1_0_kind=NetClass scope1_0_value=PWR scope2count=1 scope2_0_kind=Board scope2_0_value=Board commentlength=0 maxlimit=30 minlimit=6 preferedwidth=12
Width [All] p0: scope1count=1 scope1_0_kind=Board scope1_0_value=Board scope2count=1 scope2_0_kind=Board scope2_0_value=Board commentlength=0 maxlimit=100 minlimit=4.75 preferedwidth=5.3
Width 4mil_soc [WithinRoom('SOC_4mil')] p1: maxlimit=20 minlimit=4 preferedwidth=15 toplayer_prefwidth=4 midlayer1_prefwidth=4 midlayer3_minwidth=10 midlayer3_maxwidth=10 midlayer3_prefwidth=10 midlayer4_minwidth=10 midlayer4_maxwidth=10 midlayer4_prefwidth=10 bottomlayer_prefwidth=4 minimp=50.000000 maximp=50.000000 favimp=50.000000
Width "4 mil_mux" [WithinRoom('SOC_4mil_1') or  WithinRoom('SOC_4mil_2') or WithinRoom('SOC_4mil_3')] p2: maxlimit=15 minlimit=4.75 preferedwidth=10 toplayer_minwidth=5.3 toplayer_prefwidth=5.3 midlayer1_maxwidth=10 midlayer1_prefwidth=4.75 midlayer2_maxwidth=10 midlayer3_minwidth=5.3 midlayer3_maxwidth=10 midlayer4_minwidth=5.3 midlayer4_maxwidth=10 bottomlayer_minwidth=5.3 bottomlayer_prefwidth=5.3 minimp=50.000000 maximp=50.000000 favimp=50.000000
Width PWR [InNetClass('PWR')] p3: maxlimit=30 minlimit=6 preferedwidth=12 midlayer1_minwidth=8 midlayer2_minwidth=8 midlayer3_minwidth=8 midlayer4_minwidth=8 bottomlayer_minwidth=7 minimp=50.000000 maximp=50.000000 favimp=50.000000
Width [All] p4: maxlimit=100 minlimit=4.75 preferedwidth=5.3 toplayer_minwidth=5.3 midlayer1_prefwidth=4.75 midlayer2_minwidth=5.3 midlayer3_minwidth=5.3 midlayer4_minwidth=5.3 bottomlayer_minwidth=5.3 minimp=50.000000 maximp=50.000000 favimp=50.000000 checkconnectedcopper=TRUE
13 further rules are at their usual default settings.

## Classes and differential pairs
net class POWER: VBUS_XDS_5V0
component class PROC111_XDS110_2: C134 C135 C136 C137 C138 C139 C140 C141 C142 C143 C144 C145 C146 C147 C148 C149 C150 C151 C152 C153 C154 C155 C156 C234 D3 DS3 R129 R130 R131 R132 R133 R134 R135 R136 R137 R138 R139 R140 R141 R142 R143 R144 R145 R259 R260 R261 R308 R309 R310 R311 R312 R324 R325 R326 R327 TP27 TP28 TP29 TP30 U24 U25 U26 U27 U28 Y3
component class PROC111_XDS110_1: C227 C228 C230 C231 C232 C233 J34 R251 R252 R253 TP23 TP24 TP25 TP26 U44 U45
component class PROC111_Test_Automation: C183 C184 C185 C186 C187 C188 J1 J6 L4 R21 R182 R183 R184 R185 R186 R187 R188 R189 R190 R191 R192 R193 R194 R195 TP18 U35 U36
component class PROC111_System_Power_2: C157 C158 C159 C160 C161 C162 C163 C164 C165 C166 C167 C168 C169 C170 C171 C172 C173 C174 C175 C176 C177 C178 C179 C180 L2 L3 R146 R147 R148 R149 R150 R151 R152 R153 R154 R155 R156 R157 R158 R159 R160 R161 R162 R163 R295 R296 TP8 TP9 TP10 TP11 TP12 TP13 TP14 TP15 TP16 TP17 U29 U30 U31 U32
component class PROC111_System_Power_1: C101 C102 C103 C104 C105 C106 C107 C108 C109 C110 C229 C249 D1 J5 J11 J12 L1 R32 R89 R90 R91 R92 R93 R94 R95 R97 R98 R299 TP3 TP4 TP5 TP6 U18 U19 U20 U21 U47
component class PROC111_Push_Buttons: C181 C182 Q1 Q2 Q3 R177 R178 R179 R180 R181 SW2 SW3 SW4 U33 U34
component class PROC111_LED: C236 C237 D2 D4 D5 D6 D7 D8 D9 D10 D11 D12 D13 D14 DS1 DS2 Q10 Q11 Q13 R257 R262 R263 R264 R265 R266 R267 R268 R269 R270 R271 R272 R273 R274 R275 R276 R277 R278 R279 R302 R303 R304 R313 R314 R315 R317 U48
component class PROC111_Ehernet_RJ45_2: C247 J8 Q7 Q8 Q9 R230 R231 R232 R233 R234 R235 R255 TP22 U40 U41
component class PROC111_Ehernet_RJ45_1: C235 J7 Q4 Q5 Q6 R224 R225 R226 R227 R228 R229 R254 TP21 U38 U39
component class PROC111_Ehernet_PHY_2: C189 C190 C191 C192 C193 C194 C195 C196 C197 C198 C199 C200 C201 C202 C203 C204 C205 C206 C207 C208 C209 C210 FB5 FB6 R196 R197 R198 R199 R200 R201 R202 R203 R204 R205 R206 R207 R208 R209 R210 R211 R212 R213 R214 R215 R216 R217 R218 R219 R220 R221 R222 R223 R306 TP19 TP20 U37 Y4
component class PROC111_Ehernet_PHY_1: C112 C113 C114 C115 C116 C117 C118 C119 C120 C121 C122 C123 C124 C125 C126 C127 C128 C129 C130 C131 C132 C133 C240 C241 C242 FB3 FB4 R100 R101 R102 R103 R104 R105 R106 R107 R108 R109 R110 R111 R112 R113 R114 R115 R116 R117 R118 R119 R120 R121 R122 R123 R124 R125 R126 R127 R128 R291 R292 R293 R294 R305 TP7 U22 U50 Y2
component class PROC111_Breakout_Headers: C211 C212 C213 C214 C215 C216 C217 C218 C219 C220 C221 C222 C223 C224 C225 C226 J15 J16 J17 J18 J23 J24 J25 J33 R236 R237 R238 R239 R240 R241 R242 R243 R244 R245 R246 R247 R248 R249 R250 R328 R329 R330 R331 R332 R333 R334 R335 U42 U43
component class PROC111_Boosterpack_Headers: C243 C244 C245 C246 J1/J3 J2/J4 J5/J7 J6/J8 J9 J10 J13 J14 R256 R298 R300 U51 U52
component class PROC111_AM263x_Serial_Connectivity: R164 R165 R166 R167 R168 R169 R170 R171 R172 R173 R174 R175 R176 R297
component class PROC111_AM263x_7_PRU: C43 C111 C238 C239 C248 R71 R72 R73 R74 R75 R76 R77 R78 R79 R80 R81 R82 R83 R84 R85 R86 R87 R88 R96 R286 R287 R288 R289 R290 U23 U46 U49
component class PROC111_AM263x_6_RGMII_MII: C100 R61 R62 R63 R64 R65 R66 R67 R68 R69 R70 U17
component class PROC111_AM263x_5_ePWM_eQEP_FSI: R9 R12 R13 R46 R47 R48 R49 R50 R51 R52 R53 R54 R55 R56 R57 R58 R59 R60 R99 R280 R281 R282 R283 R284 R285
component class PROC111_AM263x_3_QSPI_MMC: C66 C67 C68 C69 C70 C71 J2 R26 R27 R28 R29 R30 R31 R33 R34 R35 R36 R37 R38 R39 R40 R41 R42 R43 U7 U8 U9 U10 U11
component class PROC111_AM263x_2_Clock_Reset_Boot_JTAG: C57 C58 C59 C60 C61 C62 C63 C64 C65 C99 R4 R5 R6 R7 R8 R10 R11 R14 R15 R16 R17 R18 R19 R20 R22 R23 R24 R25 R258 R316 R318 R319 R320 R321 R322 R323 SW1 TP1 TP2 U2 U3 U4 U5 U6 U16 Y1
component class PROC111_AM263x_1_Power: C1 C2 C3 C4 C5 C6 C7 C8 C9 C10 C11 C12 C13 C14 C15 C16 C17 C18 C19 C20 C21 C22 C23 C24 C25 C26 C27 C28 C29 C30 C31 C32 C33 C34 C35 C36 C37 C38 C39 C40 C41 C42 C44 C45 C46 C47 C48 C49 C50 C51 C52 C53 C54 C55 C56 C98 FB1 FB2 R1 R2
component class PROC111_AM263x_4_ADC_DAC: C72 C73 C74 C75 C76 C77 C78 C79 C80 C81 C82 C83 C84 C85 C86 C87 C88 C89 C90 C91 C92 C93 C94 C95 C96 C97 D15 D16 R3 R44 R45 R307 S1 S2 U1 U12 U13 U14 U15
component class PROC111_Hardware: FID1 FID2 FID3 LBL1 Logo1 Logo2 Logo3 Logo4 SH-J1 SH-J2 SH-J3 SH-J4 SH-J5 SH-J6 SH-J7 ZZ1 ZZ2 ZZ3 ZZ4
differential pair XDSET_1_D: +XDSET_1_D_P -XDSET_1_D_N
differential pair ETH2_TD_D: +ETH2_TD_D_P -ETH2_TD_D_N
differential pair ETH2_TD_C: +ETH2_TD_C_P -ETH2_TD_C_N
differential pair ETH2_TD_B: +ETH2_TD_B_P -ETH2_TD_B_N
differential pair ETH2_TD_A: +ETH2_TD_A_P -ETH2_TD_A_N
differential pair ETH1_TD_D: +ETH1_TD_D_P -ETH1_TD_D_N
differential pair ETH1_TD_C: +ETH1_TD_C_P -ETH1_TD_C_N
differential pair ETH1_TD_B: +ETH1_TD_B_P -ETH1_TD_B_N
differential pair ETH1_TD_A: +ETH1_TD_A_P -ETH1_TD_A_N
differential pair " ": +CANA_P -CANA_N

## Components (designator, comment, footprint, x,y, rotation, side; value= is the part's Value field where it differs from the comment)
C1 "C1608X7S1A335K080AC" 0603 3338.57,980.78 r270 bottom
C2 "C1608X7S1A335K080AC" 0603 3262.14,980.78 r270 bottom
C3 "C1608X7S1A335K080AC" 0603 3288.51,1364.76 r90 bottom
C4 "C1608X7S1A335K080AC" 0603 4200,1381.81 r0 bottom
C5 "C1608X7S1A335K080AC" 0603 3896.57,1501.5 r90 bottom
C6 "C1608X7S1A335K080AC" 0603 3619.13,1501.5 r90 bottom
C7 "GRM155R70J104KA01D" 0402 3603.63,743.75 r270 bottom
C8 "GRM155R70J104KA01D" 0402 4192.18,952.97 r0 bottom
C9 "GRM155R70J104KA01D" 0402 4193.67,890 r0 bottom
C10 "GRM155R70J104KA01D" 0402 3756.08,1499.91 r90 bottom
C11 "GRM155R70J104KA01D" 0402 3831.66,1499.91 r90 bottom
C12 "GRM155R70J104KA01D" 0402 4100.67,1498.22 r90 bottom
C13 "GRM155R70J104KA01D" 0402 4186.18,1317.07 r0 bottom
C14 "C1608X7S1A335K080AC" 0603 3435,824.72 r180 bottom
C15 "GRM155R70J104KA01D" 0402 3553.63,743.75 r270 bottom
C16 "GRM155R70J104KA01D" 0402 3688.87,1499.91 r90 bottom
C17 "GRM155R70J104KA01D" 0402 4190.85,1013.32 r0 bottom
C18 "GRM155R70J104KA01D" 0402 4186.18,1254.06 r0 bottom
C19 "GRM033C80J105ME05D" FP-GRM033C80J105ME05D_0201-MFG 3956.58,1193.07 r90 bottom
C20 "GRM033C80J105ME05D" FP-GRM033C80J105ME05D_0201-MFG 3445.84,994.56 r90 bottom
C21 "GRM033C80J105ME05D" FP-GRM033C80J105ME05D_0201-MFG 3395.84,1352.29 r270 bottom
C22 "GRM033C80J105ME05D" FP-GRM033C80J105ME05D_0201-MFG 3916.09,1115.08 r0 bottom
C23 "C1608X7S1A335K080AC" 0603 4107.94,624.92 r0 bottom
C24 "GRM155R70J104KA01D" 0402 4100.96,554.26 r0 bottom
C25 "C1608X7S1A335K080AC" 0603 3875,540.45 r180 bottom
C26 "GRM155R70J104KA01D" 0402 3875.31,608.97 r180 bottom
C27 "GRM155R70J104KA01D" 0402 3875.31,658.97 r180 bottom
C28 "GRM155R70J104KA01D" 0402 3875.31,708.97 r180 bottom
C29 "GRM033C80J105ME05D" FP-GRM033C80J105ME05D_0201-MFG 3445.84,1108.91 r270 bottom
C30 "GRM033C80J105ME05D" FP-GRM033C80J105ME05D_0201-MFG 3815,1273.75 r180 bottom
C31 "GRM033C80J105ME05D" FP-GRM033C80J105ME05D_0201-MFG 3814.85,1239.57 r180 bottom
C32 "GRM033C80J105ME05D" FP-GRM033C80J105ME05D_0201-MFG 3445.84,1234.32 r90 bottom
C33 "GRM188Z71A475ME15D" 0603 3738.88,569.08 r0 bottom
C34 "GRM155R70J104KA01D" 0402 3736.38,658.97 r0 bottom
C35 "GRM155R70J104KA01D" 0402 4139.44,717.13 r270 bottom
C36 "GRM155R70J104KA01D" 0402 3736.38,708.97 r0 bottom
C37 "GRM155R70J104KA01D" 0402 3739.61,493 r0 bottom
C38 "GRM155R70J104KA01D" 0402 3531.39,509.65 r90 bottom
C39 "GRM033C80J105ME05D" FP-GRM033C80J105ME05D_0201-MFG 3956.58,973 r90 bottom
C40 "GRM033C80J105ME05D" FP-GRM033C80J105ME05D_0201-MFG 3395.84,1108.91 r270 bottom
C41 "GRM033C80J105ME05D" FP-GRM033C80J105ME05D_0201-MFG 3673,1193.07 r90 bottom
C42 "GRM033C80J105ME05D" FP-GRM033C80J105ME05D_0201-MFG 3348.24,1352.29 r270 bottom
C43 "GRM155R71E104KE14D" 0402 5975,914.8 r180 top
C44 "GRM033C80J105ME05D" FP-GRM033C80J105ME05D_0201-MFG 3395.84,1234.06 r90 bottom
C45 "GRM033C80J105ME05D" FP-GRM033C80J105ME05D_0201-MFG 3395.84,994.56 r90 bottom
C46 "GRM033C80J105ME05D" FP-GRM033C80J105ME05D_0201-MFG 3693.17,1115.1 r270 bottom
C47 "GRM033C80J105ME05D" FP-GRM033C80J105ME05D_0201-MFG 3956.58,1060.9 r90 bottom
C48 "GRM155R70J104KA01D" 0402 3287.47,633.24 r270 top
C49 "GRM033Z71C104KE14D" 0201 3445.84,1352.29 r90 bottom
C50 "GRM033Z71C104KE14D" 0201 3814.85,946.1 r90 bottom
C51 "GRM033Z71C104KE14D" 0201 3892.96,1257.37 r0 bottom
C52 "C1608X7S1A335K080AC" 0603 3295,1126.61 r90 bottom
C53 "C1608X7S1A335K080AC" 0603 3210,1364.76 r90 bottom
C54 "GRM033Z71C104KE14D" 0201 3654.78,1115.1 r90 bottom
C55 "GRM033Z71C104KE14D" 0201 3990,1115.08 r180 bottom
C56 "GRM033Z71C104KE14D" 0201 3673,1004.38 r90 bottom
C57 "GRM155R71E104KE14D" 0402 2162.4,1279.45 r180 top
C58 "GRM1555C1E120JA01D" 0402 3355,741.21 r270 top
C59 "GRM1555C1E120JA01D" 0402 3355,854.33 r90 top
C60 "GRM155R71E104KE14D" 0402 3215,418.33 r0 top
C61 "GRM155R71E104KE14D" 0402 3653.69,81.97 r90 bottom
C62 "GRM155R71E104KE14D" 0402 3713.69,81.97 r90 bottom
C63 "GRM155R71E103KA01D" 0402 2207.84,767.39 r90 top
C64 "GRM155R71E104KE14D" 0402 2017.57,746.48 r270 top
C65 "GRM155R71E104KE14D" 0402 2029.22,1024.86 r0 top
C66 "GRM155R71E104KE14D" 0402 2973.62,854.15 r180 top
C67 "GRM188Z71C475KE21D" 0603 611.03,672.69 r90 top
C68 "C1608X7S1A335K080AC" 0603 924.76,669.66 r90 top
C69 "GRM155R70J104KA01D" 0402 862.1,661.79 r90 top
C70 "GRM155R71E104KE14D" 0402 2149.39,1500 r180 bottom
C71 "GRM155R71E104KE14D" 0402 587.8,785.43 r180 bottom
C72 "GRM155R70J104KA01D" 0402 1745,571.95 r90 top
C73 "GRM155R70J104KA01D" 0402 1805,571.95 r90 top
C74 "GRM155R70J104KA01D" 0402 1865,571.95 r90 top
C75 "GRM155R70J104KA01D" 0402 1924,571.95 r90 top
C76 "GRM188Z71A475ME15D" 0603 3713.17,666.5 r270 top
C77 "GRM188Z71A475ME15D" 0603 3855,727.37 r270 top
C78 "GRM155R70J104KA01D" 0402 3720.36,789.94 r0 bottom
C79 "GRM155R70J104KA01D" 0402 3844.81,789.94 r0 bottom
C80 "GRM155R70J104KA01D" 0402 3948.62,789.94 r180 bottom
C81 "GRM155R70J104KA01D" 0402 2090,572.47 r90 top
C82 "GRM155R70J104KA01D" 0402 2150,572.47 r90 top
C83 "GRM155R70J104KA01D" 0402 2210,572.47 r90 top
C84 "GRM155R70J104KA01D" 0402 2269,572.47 r90 top
C85 "GRM155R70J104KA01D" 0402 4747.11,585.15 r90 top
C86 "GRM155R70J104KA01D" 0402 4802.11,585.15 r90 top
C87 "GRM155R70J104KA01D" 0402 4856.7,585.15 r90 top
C88 "GRM155R70J104KA01D" 0402 4911.11,585.15 r90 top
C89 "GRM188Z71A475ME15D" 0603 3015,660 r90 bottom
C90 "GRM155R70J104KA01D" 0402 3595,594.91 r270 bottom
C91 "GRM155R70J104KA01D" 0402 3590,595 r270 top
C92 "GRM155R70J104KA01D" 0402 4965,586 r90 top
C93 "GRM155R70J104KA01D" 0402 5017.97,585.3 r90 top
C94 "GRM155R70J104KA01D" 0402 5073,585.3 r90 top
C95 "GRM155R70J104KA01D" 0402 5128.54,585.3 r90 top
C96 "GRM155R70J104KA01D" 0402 4339.72,549.93 r90 top
C97 "GRM155R70J104KA01D" 0402 2010,571.38 r90 top
C98 "GRM155R70J104KA01D" 0402S 3494.98,1177.95 r180 bottom
C99 "GRM155R71E104KE14D" 0402 5570,487.03 r180 bottom
C100 "GRM155R71E104KE14D" 0402 4735,1152.06 r0 bottom
C101 "GCM188R71C104KA37J" 0603 420.79,454.11 r180 top
C102 "GRM32ER7YA106KA12K" 1210_270 1149.04,689.61 r90 top
C103 "GRM188R72A104KA35J" 0603 1260,669.61 r90 top
C104 "GRM32ER7YA106KA12K" 1210_270 1390.89,700.82 r90 top
C105 "GRM32ER7YA106KA12K" 1210_270 1550,835 r90 bottom
C106 "GCM188R71C104KA37J" 0603 1579.67,844.07 r90 top
C107 "GRM32ER7YA106KA12K" 1210_270 1755.65,835 r90 bottom
C108 "GCM188R71C104KA37J" 0603 1776.91,844.07 r90 top
C109 "GRM155R71C102KA01D" 0402 1771.58,710 r270 top
C110 "GCM188R71C104KA37J" 0603 740,493.54 r90 top
C111 "GRM155R71E104KE14D" 0402 5009,992.82 r0 top
C112 "GRM1555C1E120JA01D" 0402 6728.01,381.88 r270 bottom
C113 "GRM1555C1E120JA01D" 0402 6728.01,489.12 r90 bottom
C114 "GRM188Z71A106MA73D" 0603 6279,1343.28 r90 top
C115 "GRM155R70J103KA01D" 0402 6344,1343.28 r90 top
C116 "GRM155R70J105MA12D" 0402 6556.28,941.71 r90 top
C117 "GRM155R70J104KA01D" 0402 6556.28,945.08 r90 bottom
C118 "GRM155R70J105MA12D" 0402 6493.94,745.04 r0 top
C119 "GRM155R70J104KA01D" 0402 6374.14,745.04 r180 top
C120 "GRM155R70J105MA12D" 0402 6755.41,729.88 r180 top
C121 "GRM155R70J104KA01D" 0402 6870.21,729.88 r0 bottom
C122 "GRM188Z71A106MA73D" 0603 6210,1003.65 r90 top
C123 "GRM155R70J103KA01D" 0402 6280.09,987.15 r90 top
C124 "GRM155R70J105MA12D" 0402 6755.41,670.83 r180 top
C125 "GRM155R70J104KA01D" 0402 6870.21,670.83 r0 bottom
C126 "GRM155R70J105MA12D" 0402 6755.41,788.94 r180 top
C127 "GRM155R70J104KA01D" 0402 6870.21,788.94 r0 bottom
C128 "GRM188Z71A106MA73D" 0603 6351.36,621.24 r180 bottom
C129 "GRM155R70J103KA01D" 0402 6355.51,681.97 r180 bottom
C130 "GRM155R70J105MA12D" 0402 6625,622.13 r90 top
C131 "GRM155R70J104KA01D" 0402 6670,495 r270 bottom
C132 "GRM155R70J105MA12D" 0402 6493.94,695.04 r0 top
C133 "GRM155R70J104KA01D" 0402 6379.14,695.04 r180 top
C134 "GRM155R71E104KE14D" 0402 1205.5,974.22 r180 bottom
C135 "GRM155R71E103KA01D" 0402 325,1105.38 r270 bottom
C136 "GRM155R71E104KE14D" 0402 1607.87,1117.23 r180 top
C137 "GRM155R71E104KE14D" 0402 1607.87,1340 r180 top
C138 "GRM155R71E104KE14D" 0402 1607.87,1723.86 r180 top
C139 "GRM155R71E104KE14D" 0402 1199.79,1115.27 r0 top
C140 "GRM155R71E104KE14D" 0402 1199.79,1340 r0 top
C141 "GRM155R71E104KE14D" 0402 1186.93,1723.86 r0 top
C142 "GRM155R71E104KE14D" 0402 1191.36,1554.93 r0 bottom
C143 "GCM1555C1H8R0DA16D" 0402 1192.72,1141.33 r90 bottom
C144 "GCM1555C1H8R0DA16D" 0402 1192.72,1256.13 r270 bottom
C145 "GRM155R71E104KE14D" 0402 495.31,1188.47 r0 top
C146 "GCM155C71A105KE38D" 0402_070 977.49,1025.32 r270 top
C147 "GRM155R71E104KE14D" 0402 787.63,1021.22 r90 top
C148 "GCM155C71A105KE38D" 0402_070 850.81,1627.63 r90 top
C149 "GRM155R71E103KA01D" 0402 1190.5,1347.99 r0 bottom
C150 "GRM155R71E104KE14D" 0402 480.5,1505.66 r0 top
C151 "GRM155R71E104KE14D" 0402 360.82,1225.67 r270 bottom
C152 "GRM155R71E103KA01D" 0402 415.82,1225.67 r270 bottom
C153 "GRM155C81C225KE11D" 0402 1105,1221.57 r180 top
C154 "GRM155R71E104KE14D" 0402 774.98,941.85 r180 bottom
C155 "GRM155R71E104KE14D" 0402 774.98,941.85 r180 top
C156 "GCM155C71A105KE38D" 0402_070 1105,1270 r0 top
C157 "GRM21BZ71A226ME15L" 0805_HV 2477.33,1061.68 r180 top
C158 "GRM21BZ71A226ME15L" 0805_HV 2477.33,1151.68 r180 top
C159 "GRM32ER71A476ME15L" 1210_270 2460.42,1126.68 r180 bottom
C160 "GRM188R71E474KA12D" 0603 2412.84,801.68 r270 top
C161 "GRM188Z71C475KE21D" 0603 5664.06,1227.1 r90 bottom
C162 "GCM155C71A105KE38D" 0402_070 5635.58,1227.04 r90 top
C163 "GRM155R71E104KE14D" 0402 5695.21,1222.1 r90 top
